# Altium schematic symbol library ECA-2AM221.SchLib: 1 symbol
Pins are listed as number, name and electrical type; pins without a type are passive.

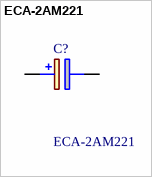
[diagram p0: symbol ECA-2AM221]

## ECA-2AM221
designator C?
PANASONIC - ECA-2AM221 - Electrolytic Capacitor, 220 F, 100 V, M Series, +/- 20%, Radial Leaded, 12.5 mm; Geometry.Height: 22mm
footprint CAPPRD500W65D1250H2200
pins: 1 +, 2 -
